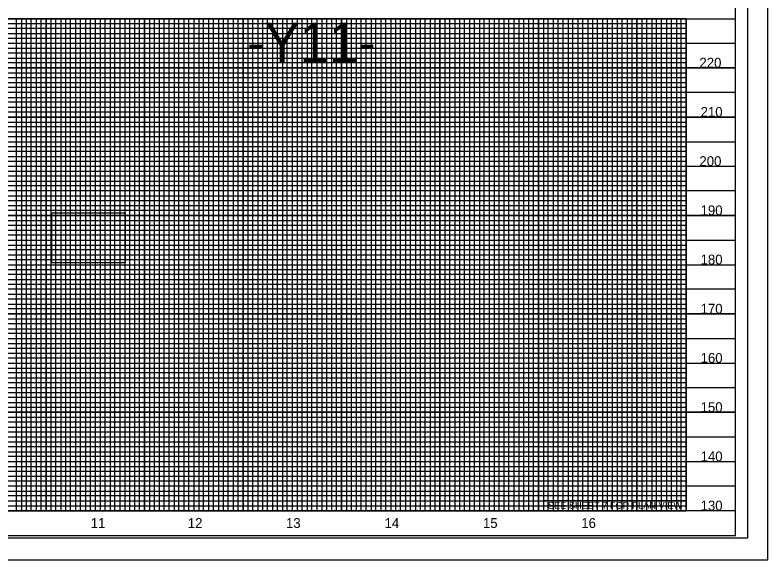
# Model space of a CAD drawing. Extents: x 1779926 to 1781626, y 618464 to 619564.
# Drawn here: x 1780862 to 1781626, y 618464 to 619018 of the extents above; entities that cross this region are included whole.
import ezdxf

# ---------------------------------------------------------------- set-up
doc = ezdxf.new("R2010")
doc.units = 0
for name, color, linetype in [('Exist Vertical Profile Horizontal Axis Label Major', 7, 'Continuous'), ('Exist Vertical Profile Vertical Axis Label', 7, 'Continuous'), ('Prop DSN Text', 7, 'Continuous'), ('Prop Grid Mask', 7, 'Continuous'), ('Sheet DOT Grid CELL', 7, 'Continuous'), ('Sheet Layout Profile Border Port 2', 7, 'Continuous'), ('Sheet Plot Border Inside CELL', 7, 'Continuous'), ('Sheet Plot Border Outside CELL', 7, 'Continuous'), ('Sheet Profile CELL', 7, 'Continuous'), ('Sheet Profile Grid Major CELL', 7, 'Continuous'), ('Sheet Profile Grid Middle CELL', 7, 'Continuous'), ('Sheet Profile Grid Minor CELL', 7, 'Continuous')]:
    doc.layers.add(name, color=color, linetype=linetype)

msp = doc.modelspace()

# ---------------------------------------------------------------- linework, layer by layer
at = {"layer": 'Prop Grid Mask'}
for points in [[(1781227.77, 619014.19), (1781092.96, 619014.19), (1781092.96, 618964.19), (1781227.77, 618964.19)], [(1780898.99, 618816.99), (1780973.24, 618816.99), (1780973.24, 618766.08), (1780898.99, 618766.08)], [(1781542.96, 618524.19), (1781397.96, 618524.19), (1781397.96, 618514.19), (1781542.96, 618514.19)]]:
    msp.add_lwpolyline(points, close=True, dxfattribs=at)
at = {"layer": 'Sheet DOT Grid CELL'}
for p, q in [((1780092.96, 619014.19), (1781592.85, 619014.19)), ((1780892.96, 619014.19), (1780892.96, 618514.19)), ((1780942.96, 619014.19), (1780942.96, 618514.19)), ((1780992.96, 619014.19), (1780992.96, 618514.19)), ((1781042.96, 619014.19), (1781042.96, 618514.19)), ((1781092.96, 619014.19), (1781092.96, 618514.19)), ((1781142.96, 619014.19), (1781142.96, 618514.19)), ((1781192.96, 619014.19), (1781192.96, 618514.19)), ((1781242.96, 619014.19), (1781242.96, 618514.19)), ((1781292.96, 619014.19), (1781292.96, 618514.19)), ((1781342.96, 619014.19), (1781342.96, 618514.19)), ((1781392.96, 619014.19), (1781392.96, 618514.19)), ((1781442.96, 619014.19), (1781442.96, 618514.19)), ((1781492.96, 619014.19), (1781492.96, 618514.19)), ((1781542.96, 619014.19), (1781542.96, 618514.19)), ((1780092.96, 618964.19), (1781592.85, 618964.19)), ((1780092.96, 618914.19), (1781592.85, 618914.19)), ((1780092.96, 618864.19), (1781592.85, 618864.19)), ((1780092.96, 618814.19), (1781592.85, 618814.19)), ((1780092.96, 618764.19), (1781592.85, 618764.19)), ((1780092.96, 618714.19), (1781592.85, 618714.19)), ((1780092.96, 618664.19), (1781592.85, 618664.19)), ((1780092.96, 618614.19), (1781592.85, 618614.19)), ((1780092.96, 618564.19), (1781592.85, 618564.19))]:
    msp.add_line(p, q, dxfattribs=at)
at = {"layer": 'Sheet Layout Profile Border Port 2'}
msp.add_line((1781542.96, 619014.19), (1781442.96, 619014.19), dxfattribs=at)
msp.add_lwpolyline([(1780142.96, 619014.19), (1781542.96, 619014.19), (1781542.96, 618514.19), (1780142.96, 618514.19)], close=True, dxfattribs=at)
msp.add_lwpolyline([(1781442.96, 619014.19), (1780142.96, 619014.19), (1780142.96, 618514.19), (1781542.96, 618514.19), (1781542.96, 619014.19)], dxfattribs=at)
at = {"layer": 'Sheet Plot Border Inside CELL'}
msp.add_lwpolyline([(1779938.96, 618486.64), (1781605.46, 618486.64), (1781605.46, 619541.74), (1779938.96, 619541.74)], close=True, dxfattribs=at)
at = {"layer": 'Sheet Plot Border Outside CELL'}
msp.add_lwpolyline([(1779925.96, 618464.19), (1781625.96, 618464.19), (1781625.96, 619564.19), (1779925.96, 619564.19)], close=True, dxfattribs=at)
at = {"layer": 'Sheet Profile CELL'}
for p, q in [((1780092.96, 619014.19), (1781592.96, 619014.19)), ((1781592.96, 618514.19), (1780092.96, 618514.19)), ((1780092.96, 618489.19), (1781592.96, 618489.19))]:
    msp.add_line(p, q, dxfattribs=at)
msp.add_lwpolyline([(1781592.96, 619539.19), (1780092.96, 619539.19), (1780092.96, 618489.19), (1781592.96, 618489.19)], close=True, dxfattribs=at)
at = {"layer": 'Sheet Profile Grid Major CELL'}
for p, q in [((1780892.96, 619014.19), (1780942.96, 619014.19)), ((1780992.96, 619014.19), (1781042.96, 619014.19)), ((1781092.96, 619014.19), (1781142.96, 619014.19)), ((1781192.96, 619014.19), (1781242.96, 619014.19)), ((1781292.96, 619014.19), (1781342.96, 619014.19)), ((1781392.96, 619014.19), (1781442.96, 619014.19)), ((1781492.96, 619014.19), (1781542.96, 619014.19)), ((1781492.96, 618514.19), (1781492.96, 618514.19))]:
    msp.add_line(p, q, dxfattribs=at)
for points in [[(1780842.96, 618514.19), (1780892.96, 618514.19), (1780892.96, 619014.19), (1780942.96, 619014.19), (1780942.96, 618514.19), (1780992.96, 618514.19), (1780992.96, 619014.19), (1781042.96, 619014.19), (1781042.96, 618514.19), (1781092.96, 618514.19), (1781092.96, 619014.19), (1781142.96, 619014.19), (1781142.96, 618514.19), (1781192.96, 618514.19), (1781192.96, 619014.19), (1781242.96, 619014.19), (1781242.96, 618514.19), (1781292.96, 618514.19), (1781292.96, 619014.19), (1781342.96, 619014.19), (1781342.96, 618514.19), (1781392.96, 618514.19), (1781392.96, 619014.19), (1781442.96, 619014.19), (1781442.96, 618514.19), (1781492.96, 618514.19), (1781492.96, 618514.19), (1781492.96, 619014.19), (1781542.96, 619014.19), (1781542.96, 618514.19)], [(1781592.96, 618964.19), (1780092.96, 618964.19)], [(1781592.96, 618914.19), (1780092.96, 618914.19), (1780092.96, 618864.19), (1781592.96, 618864.19)], [(1781592.96, 618814.19), (1780092.96, 618814.19), (1780092.96, 618764.19), (1781592.96, 618764.19)], [(1781592.96, 618714.19), (1780092.96, 618714.19), (1780092.96, 618664.19), (1781592.96, 618664.19)], [(1781592.96, 618614.19), (1780092.96, 618614.19), (1780092.96, 618614.19), (1780092.96, 618564.19), (1781592.96, 618564.19)], [(1781592.96, 618514.19), (1780092.96, 618514.19)]]:
    msp.add_lwpolyline(points, dxfattribs=at)
at = {"layer": 'Sheet Profile Grid Middle CELL'}
for points in [[(1780817.96, 619014.19), (1780867.96, 619014.19), (1780867.96, 618514.19), (1780917.96, 618514.19), (1780917.96, 619014.19), (1780967.96, 619014.19), (1780967.96, 618514.19), (1781017.96, 618514.19), (1781017.96, 619014.19), (1781067.96, 619014.19), (1781067.96, 618514.19), (1781117.96, 618514.19), (1781117.96, 619014.19), (1781167.96, 619014.19), (1781167.96, 618514.19), (1781217.96, 618514.19), (1781217.96, 619014.19), (1781267.96, 619014.19), (1781267.96, 618514.19), (1781317.96, 618514.19), (1781317.96, 619014.19), (1781367.96, 619014.19), (1781367.96, 618514.19), (1781417.96, 618514.19), (1781417.96, 619014.19), (1781467.96, 619014.19), (1781467.96, 618514.19), (1781517.96, 618514.19), (1781517.96, 619014.19)], [(1780092.96, 618989.19), (1781592.96, 618989.19)], [(1781592.96, 618939.19), (1780092.96, 618939.19), (1780092.96, 618889.19), (1781592.96, 618889.19)], [(1781592.96, 618839.19), (1780092.96, 618839.19), (1780092.96, 618789.19), (1781592.96, 618789.19)], [(1781592.96, 618739.19), (1780092.96, 618739.19), (1780092.96, 618689.19), (1781592.96, 618689.19)], [(1781592.96, 618639.19), (1780092.96, 618639.19), (1780092.96, 618589.19), (1781592.96, 618589.19)], [(1781592.96, 618539.19), (1780092.96, 618539.19)]]:
    msp.add_lwpolyline(points, dxfattribs=at)
at = {"layer": 'Sheet Profile Grid Minor CELL'}
for p, q in [((1780142.96, 619009.19), (1781542.96, 619009.19)), ((1781542.96, 619004.19), (1780142.96, 619004.19)), ((1780142.96, 618999.19), (1781542.96, 618999.19)), ((1781542.96, 618994.19), (1780142.96, 618994.19)), ((1780142.96, 618984.19), (1781542.96, 618984.19)), ((1781542.96, 618979.19), (1780142.96, 618979.19)), ((1780142.96, 618974.19), (1781542.96, 618974.19)), ((1781542.96, 618969.19), (1780142.96, 618969.19)), ((1780142.96, 618959.19), (1781542.96, 618959.19)), ((1781542.96, 618954.19), (1780142.96, 618954.19)), ((1780142.96, 618949.19), (1781542.96, 618949.19)), ((1781542.96, 618944.19), (1780142.96, 618944.19)), ((1780142.96, 618934.19), (1781542.96, 618934.19)), ((1781542.96, 618929.19), (1780142.96, 618929.19)), ((1780142.96, 618924.19), (1781542.96, 618924.19)), ((1781542.96, 618919.19), (1780142.96, 618919.19)), ((1780142.96, 618909.19), (1781542.96, 618909.19)), ((1781542.96, 618904.19), (1780142.96, 618904.19)), ((1780142.96, 618899.19), (1781542.96, 618899.19)), ((1781542.96, 618894.19), (1780142.96, 618894.19)), ((1780142.96, 618884.19), (1781542.96, 618884.19)), ((1781542.96, 618879.19), (1780142.96, 618879.19)), ((1780142.96, 618874.19), (1781542.96, 618874.19)), ((1781542.96, 618869.19), (1780142.96, 618869.19)), ((1780142.96, 618859.19), (1781542.96, 618859.19)), ((1781542.96, 618854.19), (1780142.96, 618854.19)), ((1780142.96, 618849.19), (1781542.96, 618849.19)), ((1781542.96, 618844.19), (1780142.96, 618844.19)), ((1780142.96, 618834.19), (1781542.96, 618834.19)), ((1781542.96, 618829.19), (1780142.96, 618829.19)), ((1780142.96, 618824.19), (1781542.96, 618824.19)), ((1781542.96, 618819.19), (1780142.96, 618819.34)), ((1780142.96, 618809.19), (1781542.96, 618809.19)), ((1781542.96, 618804.19), (1780142.96, 618804.19)), ((1780142.96, 618799.19), (1781542.96, 618799.19)), ((1781542.96, 618794.19), (1780142.96, 618794.19)), ((1780142.96, 618784.19), (1781542.96, 618784.19)), ((1781542.96, 618779.19), (1780142.96, 618779.19)), ((1780142.96, 618774.19), (1781542.96, 618774.19)), ((1781542.96, 618769.19), (1780142.96, 618769.19)), ((1780142.96, 618759.19), (1781542.96, 618759.19)), ((1781542.96, 618754.19), (1780142.96, 618754.19)), ((1780142.96, 618749.19), (1781542.96, 618749.19)), ((1781542.96, 618744.19), (1780142.96, 618744.19)), ((1780142.96, 618734.19), (1781542.96, 618734.19)), ((1781542.96, 618729.19), (1780142.96, 618729.19)), ((1780142.96, 618724.19), (1781542.96, 618724.19)), ((1781542.96, 618719.19), (1780142.96, 618719.19)), ((1780142.96, 618709.19), (1781542.96, 618709.19)), ((1781542.96, 618704.19), (1780142.96, 618704.19)), ((1780142.96, 618699.19), (1781542.96, 618699.19)), ((1781542.96, 618694.19), (1780142.96, 618694.19)), ((1780142.96, 618684.19), (1781542.96, 618684.19)), ((1781542.96, 618679.19), (1780142.96, 618679.19)), ((1780142.96, 618674.19), (1781542.96, 618674.19)), ((1781542.96, 618669.19), (1780142.96, 618669.19)), ((1780142.96, 618659.19), (1781542.96, 618659.19)), ((1781542.96, 618654.19), (1780142.96, 618654.19)), ((1780142.96, 618649.19), (1781542.96, 618649.19)), ((1781542.96, 618644.19), (1780142.96, 618644.19)), ((1780142.96, 618634.19), (1781542.96, 618634.19)), ((1781542.96, 618629.19), (1780142.96, 618629.19)), ((1780142.96, 618624.19), (1781542.96, 618624.19)), ((1781542.96, 618619.19), (1780142.96, 618619.19)), ((1780142.96, 618609.19), (1781542.96, 618609.19)), ((1781542.96, 618604.19), (1780142.96, 618604.19)), ((1780142.96, 618599.19), (1781542.96, 618599.19)), ((1781542.96, 618594.19), (1780142.96, 618594.19)), ((1780142.96, 618584.19), (1781542.96, 618584.19)), ((1781542.96, 618579.19), (1780142.96, 618579.19)), ((1780142.96, 618574.19), (1781542.96, 618574.19)), ((1781542.96, 618569.19), (1780142.96, 618569.19)), ((1780142.96, 618559.19), (1781542.96, 618559.19)), ((1781542.96, 618554.19), (1780142.96, 618554.19)), ((1780142.96, 618549.19), (1781542.96, 618549.19)), ((1781542.96, 618544.19), (1780142.96, 618544.19)), ((1780142.96, 618534.19), (1781542.96, 618534.19)), ((1781542.96, 618529.19), (1780142.96, 618529.19)), ((1780142.96, 618524.19), (1781542.96, 618524.19)), ((1780142.96, 618519.19), (1781542.96, 618519.19)), ((1781542.96, 618519.19), (1781542.96, 618519.19))]:
    msp.add_line(p, q, dxfattribs=at)
for points in [[(1780857.96, 618514.19), (1780862.96, 618514.19), (1780862.96, 619014.19), (1780872.96, 619014.19), (1780872.96, 618514.19), (1780877.96, 618514.19), (1780877.96, 619014.19), (1780882.96, 619014.19), (1780882.96, 618514.19), (1780887.96, 618514.19), (1780887.96, 619014.19), (1780897.96, 619014.19), (1780897.96, 618514.19), (1780902.96, 618514.19), (1780902.96, 619014.19), (1780907.96, 619014.19), (1780907.96, 618514.19), (1780912.96, 618514.19), (1780912.96, 619014.19), (1780922.96, 619014.19), (1780922.96, 618514.19), (1780927.96, 618514.19), (1780927.96, 619014.19), (1780932.96, 619014.19), (1780932.96, 618514.19), (1780937.96, 618514.19), (1780937.96, 619014.19), (1780947.96, 619014.19), (1780947.96, 618514.19), (1780952.66, 618514.74), (1780952.96, 618514.19), (1780952.96, 619014.19), (1780957.96, 619014.19), (1780957.96, 618514.19), (1780962.96, 618514.19), (1780962.96, 619014.19), (1780972.96, 619014.19), (1780972.96, 618514.19), (1780977.96, 618514.19)], [(1780977.96, 618514.19), (1780977.96, 619014.19), (1780982.96, 619014.19), (1780982.96, 618514.19), (1780987.96, 618514.19), (1780987.96, 619014.19), (1780997.96, 619014.19), (1780997.96, 618514.19), (1781002.96, 618514.19), (1781002.96, 619014.19), (1781007.96, 619014.19), (1781007.96, 618514.19), (1781012.96, 618514.19), (1781012.96, 619014.19), (1781022.96, 619014.19), (1781022.96, 618514.19), (1781027.96, 618514.19), (1781027.96, 619014.19), (1781032.96, 619014.19), (1781032.96, 618514.19), (1781037.96, 618514.19), (1781037.96, 619014.19), (1781047.96, 619014.19), (1781047.96, 618514.19), (1781052.96, 618514.19), (1781052.96, 619014.19), (1781057.96, 619014.19), (1781057.96, 618514.19), (1781062.96, 618514.19), (1781062.96, 619014.19), (1781072.96, 619014.19), (1781072.96, 618514.19), (1781077.96, 618514.19), (1781077.96, 619014.19), (1781082.96, 619014.19), (1781082.96, 618514.19), (1781087.96, 618514.19), (1781087.96, 619014.19), (1781097.96, 619014.19), (1781097.96, 618514.19), (1781102.96, 618514.19), (1781102.96, 619014.19), (1781107.96, 619014.19), (1781107.96, 618514.19), (1781112.96, 618514.19), (1781112.96, 619014.19), (1781122.96, 619014.19), (1781122.96, 618514.19), (1781127.96, 618514.19), (1781127.96, 619014.19), (1781132.96, 619014.19), (1781132.96, 618514.19), (1781137.96, 618514.19), (1781137.96, 619014.19), (1781147.96, 619014.19), (1781147.96, 618514.19), (1781152.96, 618514.19), (1781152.96, 619014.19), (1781157.96, 619014.19), (1781157.96, 618514.19), (1781162.96, 618514.19), (1781162.96, 619014.19), (1781172.96, 619014.19), (1781172.96, 618514.19), (1781177.96, 618514.19), (1781177.96, 619014.19), (1781182.96, 619014.19), (1781182.96, 618514.19), (1781187.96, 618514.19), (1781187.96, 619014.19), (1781197.96, 619014.19), (1781197.96, 618514.19), (1781202.96, 618514.19), (1781202.96, 619014.19), (1781207.96, 619014.19), (1781207.96, 618514.19), (1781212.96, 618514.19), (1781212.96, 619014.19), (1781222.96, 619014.19), (1781222.96, 618514.19), (1781227.96, 618514.19), (1781227.96, 619014.19), (1781232.96, 619014.19), (1781232.96, 618514.19), (1781237.96, 618514.19), (1781237.96, 619014.19), (1781247.96, 619014.19), (1781247.96, 618514.19), (1781252.96, 618514.19), (1781252.96, 619014.19), (1781257.96, 619014.19), (1781257.96, 618514.19), (1781262.96, 618514.19), (1781262.96, 619014.19), (1781272.96, 619014.19), (1781272.96, 618514.19), (1781277.96, 618514.19), (1781277.96, 619014.19), (1781282.96, 619014.19), (1781282.96, 618514.19)], [(1781282.96, 618514.19), (1781287.96, 618514.19), (1781287.96, 619014.19), (1781297.96, 619014.19), (1781297.96, 618514.19), (1781302.96, 618514.19), (1781302.96, 619014.19), (1781307.96, 619014.19), (1781307.96, 618514.19), (1781312.96, 618514.19), (1781312.96, 619014.19), (1781322.96, 619014.19), (1781322.96, 618514.19), (1781327.96, 618514.19), (1781327.96, 619014.19), (1781332.96, 619014.19), (1781332.96, 618514.19), (1781337.96, 618514.19), (1781337.96, 619014.19), (1781347.96, 619014.19), (1781347.96, 618514.19), (1781352.96, 618514.19), (1781352.96, 619014.19), (1781357.96, 619014.19), (1781357.96, 618514.19), (1781362.96, 618514.19), (1781362.96, 619014.19), (1781372.96, 619014.19), (1781372.96, 618514.19), (1781377.96, 618514.19), (1781377.96, 619014.19), (1781382.96, 619014.19), (1781382.96, 618514.19), (1781387.96, 618514.19), (1781387.96, 619014.19), (1781397.96, 619014.19), (1781397.96, 618514.19), (1781402.96, 618514.19), (1781402.96, 619014.19), (1781407.96, 619014.19), (1781407.96, 618514.19), (1781412.96, 618514.19), (1781412.96, 619014.19), (1781422.96, 619014.19), (1781422.96, 618514.19), (1781427.96, 618514.19), (1781427.96, 619014.19), (1781432.96, 619014.19), (1781432.96, 618514.19), (1781437.96, 618514.19), (1781437.96, 619014.19), (1781447.96, 619014.19), (1781447.96, 618514.19), (1781452.96, 618514.19), (1781452.96, 619014.19), (1781457.96, 619014.19), (1781457.96, 618514.19), (1781462.96, 618514.19), (1781462.96, 619014.19), (1781472.96, 619014.19), (1781472.96, 618514.19), (1781477.96, 618514.19), (1781477.96, 619014.19), (1781482.96, 619014.19), (1781482.96, 618514.19), (1781487.96, 618514.19), (1781487.96, 619014.19), (1781497.96, 619014.19), (1781497.96, 618514.19), (1781502.96, 618514.19), (1781502.96, 619014.19), (1781507.96, 619014.19), (1781507.96, 618514.19), (1781512.96, 618514.19), (1781512.96, 619014.19), (1781522.96, 619014.19), (1781522.96, 618514.19), (1781527.96, 618514.19), (1781527.96, 619014.19), (1781532.96, 619014.19), (1781532.96, 618514.19), (1781537.96, 618514.19), (1781537.96, 619014.19), (1781542.96, 619014.19)]]:
    msp.add_lwpolyline(points, dxfattribs=at)

# ---------------------------------------------------------------- texts
at = {"layer": 'Exist Vertical Profile Horizontal Axis Label Major'}
for s, p in [('11', (1780938.38, 618496.69)), ('12', (1781036.93, 618496.69)), ('13', (1781136.61, 618496.69)), ('14', (1781236.66, 618496.69)), ('15', (1781336.59, 618496.69)), ('16', (1781436.42, 618496.69))]:
    msp.add_text(s, height=10, dxfattribs=at).set_placement(p)
at = {"layer": 'Exist Vertical Profile Vertical Axis Label'}
for s, p in [('220', (1781556.39, 618964.44)), ('210', (1781557.59, 618914.44)), ('200', (1781556.39, 618864.44)), ('190', (1781557.59, 618814.44)), ('180', (1781557.59, 618764.44)), ('170', (1781557.59, 618714.44)), ('160', (1781557.59, 618664.44)), ('150', (1781557.59, 618614.44)), ('140', (1781557.59, 618564.44)), ('130', (1781557.59, 618514.44))]:
    msp.add_text(s, height=10, dxfattribs=at).set_placement(p)
at = {"layer": 'Prop DSN Text'}
for s, height, p in [('-Y11-', 40, (1781097.01, 618970.14)), ('SEE SHEET 7 FOR PLAN VIEW', 7, (1781402.54, 618516.14))]:
    msp.add_text(s, height=height, dxfattribs=at).set_placement(p)

doc.saveas('drawing.dxf')
